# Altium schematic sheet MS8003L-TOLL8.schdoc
size 127 x 101 mm
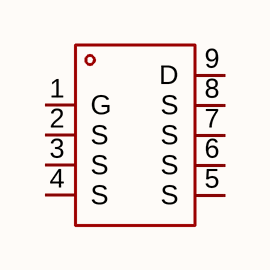
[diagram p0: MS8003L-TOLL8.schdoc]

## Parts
Q?  ms8003l-toll8  [TOLL-8_L10.4-W9.9-P1.20-LS11.7-BL]  (value not drawn)

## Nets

Not connected (* = marked no-connect by the designer): Q? 1(G) 2(S) 3(S) 4(S) 5(S) 6(S) 7(S) 8(S) 9(D)

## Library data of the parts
Q? = ms8003l-toll8: 数量:1个N沟道;漏源电压(Vdss):80V;连续漏极电流(Id):383A;导通电阻(RDS(on)):1mΩ@10V;耗散功率(Pd):358W;阈值电压(Vgs(th)):3V;; Manufacturer: MSKSEMI(美森科); AddInBom: yes; ModelId: 8ca80fd5c5554dd79eeadaa9fc4e76f7; ModelName: TOLL_L10.4-W9.9-P1.20-LS11.7-BL_HUAYI_HYG022N10NS1TA; ModelTransform: 389.763,459.842,0,0,0,0,0,59.055,0; Number: 1个N沟道; Drain to Source Voltage: 80V; Current - Continuous Drain(Id): 383A; Pd - Power Dissipation: 358W; Gate Threshold Voltage (Vgs(th)): 3V; Gate Charge(Qg): 206nC; Input Capacitance(Ciss): 13.1nF; Reverse Transfer Capacitance (Crss@Vds): 120pF; Type: N沟道; Output Capacitance(Coss): 3.1nF; Vgs: ±20V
